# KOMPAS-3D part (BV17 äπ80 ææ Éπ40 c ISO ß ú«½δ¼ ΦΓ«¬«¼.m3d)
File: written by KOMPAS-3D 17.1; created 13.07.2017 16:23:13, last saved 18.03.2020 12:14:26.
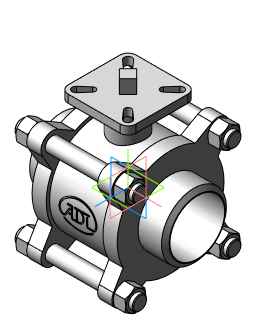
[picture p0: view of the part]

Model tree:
1. Операция без истории:1  (labels: Сталь 20  ГОСТ 1050-88)

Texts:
  DISO1
  DISO2
  BV17 Ду8 1/4" Ру63 с ISO
  BV17 Ду8 СС Ру63 с ISO
  BV17 Ду10 3/8" Ру63 с ISO
  BV17 Ду10 СС Ру63 с ISO
  BV17 Ду15 1/2" Ру63 с ISO
  BV17 Ду15 СС Ру63 с ISO
  BV17 Ду15 ФФ Ру40 с ISO
  BV17 Ду20 3/4" Ру63 с ISO
  BV17 Ду20 СС Ру40 с ISO
  BV17 Ду20 ФФ Ру40 с ISO
  BV17 Ду25 1" Ру63 с ISO
  BV17 Ду25 СС Ру63 с ISO
  BV17 Ду25 ФФ Ру40 с ISO
  BV17 Ду32 1 1/4" Ру63 с ISO
  BV17 Ду32 СС Ру63 с ISO
  BV17 Ду32 ФФ Ру40 с ISO
  BV17 Ду40 1 1/2" Ру63 с ISO
  BV17 Ду40 СС Ру63 с ISO
  BV17 Ду40 ФФ Ру40 с ISO
  BV17 Ду50 2" Ру63 с ISO
  BV17 Ду50 СС Ру63 с ISO
  BV17 Ду50 ФФ Ру40 с ISO
  BV17 Ду65 2 1/2" Ру40 с ISO
  BV17 Ду65 СС Ру40 с ISO
  BV17 Ду65 ФФ Ру40 с ISO
  BV17 Ду80 3" Ру40 с ISO
  BV17 Ду80 СС Ру40 с ISO
  BV17 Ду80 ФФ Ру40 с ISO
  BV17 Ду100 4" Ру40 с ISO
  BV17 Ду100 СС Ру40 с ISO
  BV17 Ду100 ФФ Ру40 с ISO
